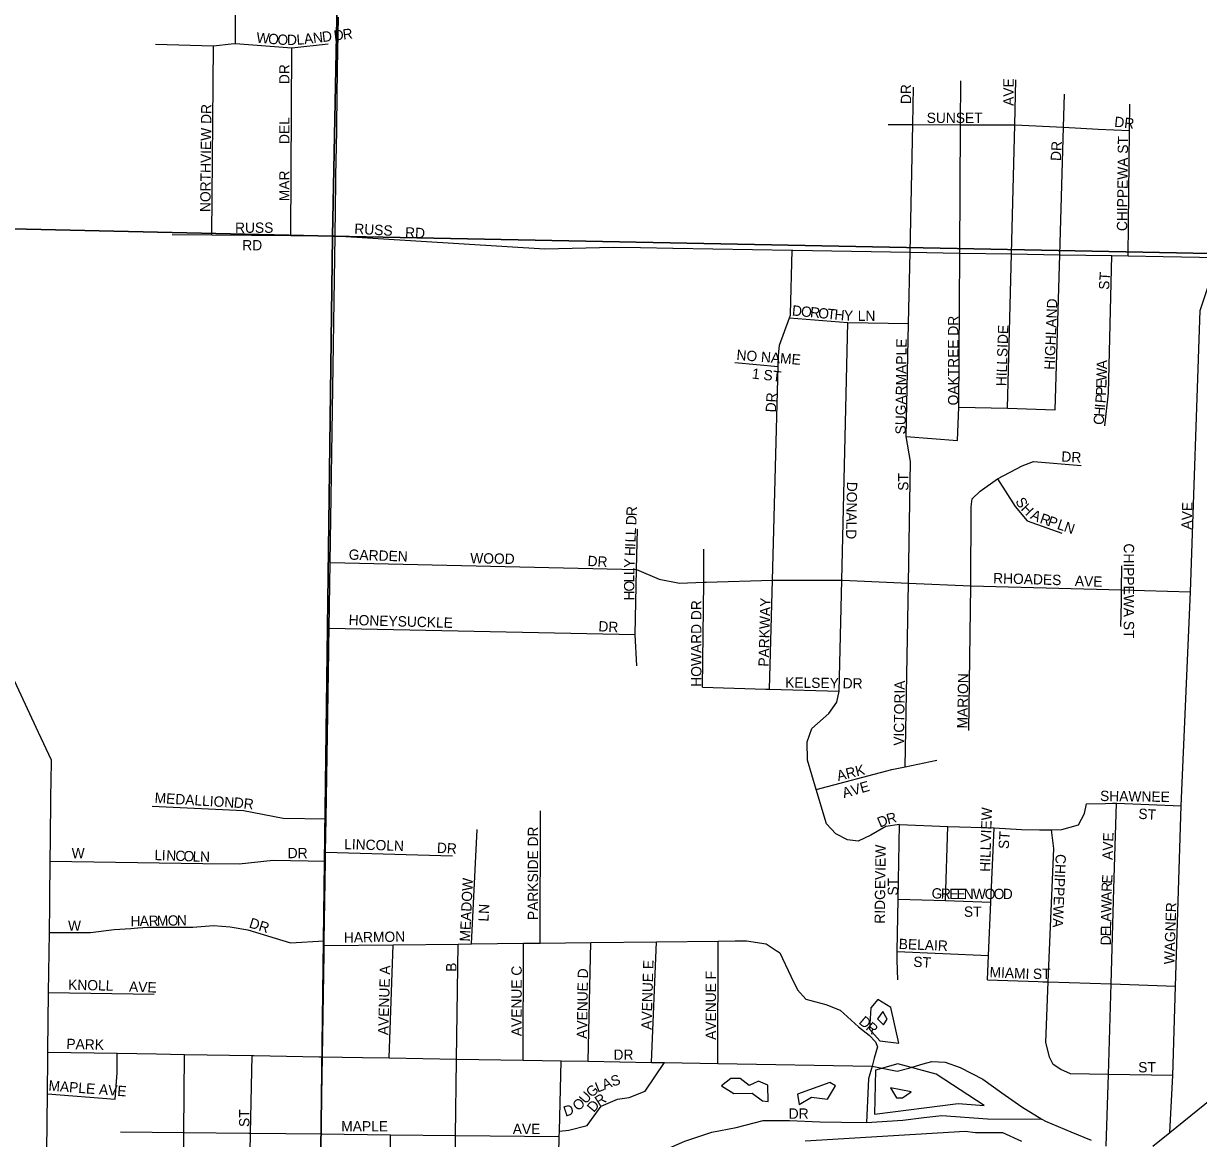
# Model space of a CAD drawing. Extents: x -784 to 1375, y -225 to 440.
# Drawn here: x 287.9 to 310.15, y 368.36 to 389.47 of the extents above; entities that cross this region are included whole.
import ezdxf

# ---------------------------------------------------------------- set-up
doc = ezdxf.new("R2010")
doc.units = 0
for name, color, linetype in [('GM_X_City_Street', 7, 'Continuous'), ('GM_X_City_Street_Text', 7, 'Continuous'), ('GM_X_Major_River', 7, 'Continuous'), ('GM_X_Minor_Lake', 7, 'Continuous'), ('GM_X_Section', 7, 'Continuous'), ('GM_X_State_Route', 7, 'Continuous'), ('GM_X_Township_Subdivision', 7, 'Continuous')]:
    doc.layers.add(name, color=color, linetype=linetype)

msp = doc.modelspace()

# ---------------------------------------------------------------- linework, layer by layer
at = {"layer": 'GM_X_City_Street'}
for points in [[(290.396, 389.08), (291.499, 389.046), (291.828, 389.084), (291.83, 389.084)], [(291.465, 385.468), (291.499, 389.046)], [(291.83, 389.084), (291.91, 389.093), (292.977, 389.009), (293.668, 389.089)], [(292.96, 385.456), (292.977, 389.009)], [(304.615, 381.651), (304.659, 383.79), (304.686, 385.14), (304.736, 387.556), (304.75, 388.263)], [(305.611, 382.209), (305.628, 385.124), (305.641, 387.555), (305.646, 388.384)], [(306.534, 382.188), (306.606, 385.108), (306.667, 387.554), (306.688, 388.407)], [(304.615, 381.651), (305.586, 381.577), (305.611, 382.209), (306.534, 382.188), (307.432, 382.155), (307.52, 385.092), (307.593, 387.506), (307.612, 388.136)], [(308.813, 385.07), (308.843, 387.442), (308.849, 387.944)], [(304.274, 387.557), (304.736, 387.556), (305.641, 387.555), (306.667, 387.554), (307.593, 387.506), (308.249, 387.473)], [(308.249, 387.473), (308.249, 387.473), (308.843, 387.442)], [(309.607, 368.471), (309.66, 369.552), (309.713, 371.243), (309.818, 374.657), (309.997, 378.712), (310.179, 384.035), (310.514, 385.041), (310.857, 386.101)], [(290.711, 385.475), (291.465, 385.468), (292.96, 385.456), (293.798, 385.449)], [(293.798, 385.449), (297.768, 385.203), (299.065, 385.236), (299.581, 385.228), (300.191, 385.217)], [(300.191, 385.217), (300.2, 385.217), (302.456, 385.179), (302.462, 385.178)], [(302.425, 383.956), (302.425, 383.965), (302.456, 385.179)], [(302.462, 385.178), (302.469, 385.178), (304.686, 385.14), (305.628, 385.124), (306.606, 385.108), (307.52, 385.092), (308.506, 385.075), (308.813, 385.07), (309.482, 385.059)], [(308.376, 381.851), (308.445, 382.468), (308.506, 385.075)], [(309.482, 385.059), (309.482, 385.059), (310.514, 385.041)], [(302.025, 376.867), (302.081, 378.931), (302.191, 382.973), (302.197, 383.184), (302.211, 383.379), (302.406, 383.897), (302.424, 383.945), (302.425, 383.956)], [(302.406, 383.897), (303.508, 383.81), (304.659, 383.79)], [(304.489, 374.303), (304.229, 374.263), (303.943, 374.1), (303.704, 373.99), (303.501, 374.011), (303.278, 374.128), (303.104, 374.314), (302.908, 374.969), (302.742, 375.524), (302.737, 375.869), (302.823, 376.118), (303.145, 376.405), (303.301, 376.622), (303.346, 376.83), (303.395, 378.929), (303.508, 383.81)], [(301.371, 383.052), (302.191, 382.973)], [(304.596, 375.398), (304.655, 378.875), (304.695, 381.179), (304.615, 381.651)], [(305.796, 376.081), (305.835, 378.823), (305.842, 380.32), (305.862, 380.469), (306.015, 380.613), (306.344, 380.846), (306.81, 381.096), (307.024, 381.177), (307.926, 381.101)], [(306.344, 380.846), (306.674, 380.323), (306.904, 380.051), (307.558, 379.817)], [(299.51, 377.309), (299.481, 377.898), (299.504, 379.135), (299.528, 379.895)], [(300.758, 376.902), (300.778, 378.89), (300.784, 379.519)], [(293.704, 379.266), (299.504, 379.135)], [(299.504, 379.135), (299.937, 378.95), (300.318, 378.875), (300.778, 378.89), (300.827, 378.891), (302.081, 378.931), (302.133, 378.931)], [(308.687, 378.515), (308.691, 378.747), (308.699, 379.203)], [(302.133, 378.931), (302.142, 378.931), (303.395, 378.929), (303.404, 378.929), (304.655, 378.875), (305.835, 378.823), (308.691, 378.747), (309.997, 378.712)], [(308.68, 378.052), (308.687, 378.513), (308.687, 378.515)], [(293.684, 378.021), (299.481, 377.898)], [(300.758, 376.902), (301.952, 376.869)], [(301.952, 376.869), (301.952, 376.869), (302.025, 376.867), (303.346, 376.83)], [(302.908, 374.969), (304.338, 375.346), (304.596, 375.398), (305.192, 375.519)], [(304.489, 374.303), (305.404, 374.267), (306.279, 374.24), (306.798, 374.209), (307.136, 374.202), (307.363, 374.204), (307.379, 374.204), (307.56, 374.207), (307.877, 374.294), (307.992, 374.511), (308.03, 374.693), (308.384, 374.703), (308.518, 374.707)], [(308.518, 374.707), (308.594, 374.709), (309.818, 374.657)], [(308.546, 373.085), (308.546, 373.085), (308.594, 374.709)], [(290.332, 374.651), (292.067, 374.567), (292.814, 374.426), (293.629, 374.409)], [(297.68, 372.058), (297.687, 374.559)], [(304.452, 371.364), (304.441, 371.733), (304.444, 371.897), (304.462, 372.892), (304.489, 374.303)], [(305.36, 372.861), (305.404, 374.267)], [(296.381, 372.043), (296.486, 374.211)], [(306.151, 371.359), (306.172, 371.821), (306.217, 372.831), (306.279, 374.24)], [(307.303, 371.322), (307.303, 371.328), (307.41, 373.851), (307.363, 374.204)], [(288.404, 373.606), (291.292, 373.564), (291.981, 373.558), (292.625, 373.625), (293.617, 373.61)], [(293.619, 373.782), (296.024, 373.708)], [(308.402, 368.215), (308.442, 369.57), (308.493, 371.283), (308.546, 373.085)], [(304.462, 372.892), (305.36, 372.861), (306.217, 372.831)], [(288.388, 372.257), (289.169, 372.257), (289.617, 372.314), (289.931, 372.336), (290.06, 372.344), (290.065, 372.345)], [(290.065, 372.345), (290.253, 372.357), (290.707, 372.359), (291.106, 372.362), (291.498, 372.389), (291.811, 372.364), (292.145, 372.307), (292.952, 372.062), (293.593, 372.098)], [(293.592, 372.011), (294.9, 372.026), (296.129, 372.04), (296.381, 372.043), (297.366, 372.055), (297.68, 372.058), (298.641, 372.069), (299.887, 372.083), (301.053, 372.097), (301.377, 372.1), (301.379, 372.1)], [(294.825, 369.883), (294.9, 372.026)], [(296.099, 369.84), (296.1, 369.861), (296.129, 372.04)], [(297.36, 369.84), (297.366, 372.055)], [(298.588, 369.819), (298.641, 372.069)], [(299.793, 369.798), (299.887, 372.083)], [(301.045, 369.777), (301.053, 372.097)], [(301.379, 372.1), (301.587, 372.103), (301.961, 372.044), (302.17, 371.906), (302.174, 371.903)], [(302.174, 371.903), (302.222, 371.872), (302.427, 371.434), (302.552, 371.172), (302.711, 370.994), (303.092, 370.896), (303.362, 370.786), (303.712, 370.47), (303.911, 370.315), (304.032, 370.185), (304.069, 370.09), (304.007, 369.881), (303.966, 369.727), (303.901, 369.484), (303.86, 368.662)], [(304.444, 371.897), (306.172, 371.821)], [(306.151, 371.359), (307.111, 371.328)], [(307.111, 371.328), (307.198, 371.325), (307.303, 371.322), (308.493, 371.283), (309.713, 371.243)], [(309.66, 369.552), (308.442, 369.57), (307.727, 369.581), (307.54, 369.664), (307.393, 369.761), (307.326, 369.896), (307.254, 370.18), (307.303, 371.322)], [(288.374, 371.122), (290.37, 371.091)], [(288.36, 369.993), (289.669, 369.971), (290.414, 369.958), (290.414, 369.958)], [(289.635, 369.099), (289.674, 369.6), (289.669, 369.971)], [(290.414, 369.958), (290.945, 369.949), (292.227, 369.927), (292.262, 369.927), (292.262, 369.927)], [(290.927, 367.203), (290.935, 368.472), (290.945, 369.949)], [(292.135, 365.382), (292.136, 365.399), (292.169, 367.021), (292.198, 368.458), (292.227, 369.927)], [(292.262, 369.927), (293.494, 369.906)], [(293.494, 369.906), (293.494, 369.906), (293.56, 369.904), (294.315, 369.891)], [(294.315, 369.891), (294.315, 369.891), (294.825, 369.883), (296.1, 369.861), (297.36, 369.84), (298.079, 369.827), (298.588, 369.819), (299.793, 369.798), (300.037, 369.794), (301.045, 369.777), (303.966, 369.727), (304.444, 369.633), (304.665, 369.69), (304.934, 369.77), (305.1, 369.814), (305.351, 369.8), (305.632, 369.7), (306.066, 369.478), (306.422, 369.219), (306.801, 368.96), (307.184, 368.724), (307.25, 368.683), (307.733, 368.484), (308.114, 368.327)], [(296.062, 367.039), (296.08, 368.416), (296.099, 369.84), (296.099, 369.84)], [(298.364, 366.766), (298.018, 367.055), (298.043, 368.394), (298.046, 368.496), (298.079, 369.827)], [(298.046, 368.496), (298.227, 368.514), (298.574, 368.605), (298.838, 368.97), (299.146, 369.105), (299.369, 369.131), (299.672, 369.255), (300.037, 369.794)], [(288.351, 369.202), (289.635, 369.099)], [(298.294, 366.575), (298.336, 366.731), (298.364, 366.766), (298.695, 367.183), (299.011, 367.541), (299.395, 367.804), (299.928, 368.093), (300.42, 368.306), (300.934, 368.478), (301.391, 368.566), (301.904, 368.699), (302.405, 368.699), (302.976, 368.674), (303.39, 368.669), (303.86, 368.662), (304.548, 368.706), (304.949, 368.752), (305.288, 368.791), (306.151, 368.732), (307.184, 368.724)], [(289.733, 368.485), (290.935, 368.472), (292.166, 368.459), (292.172, 368.458)], [(292.172, 368.458), (292.198, 368.458), (293.537, 368.444), (294.85, 368.429), (296.08, 368.416), (298.043, 368.394)], [(294.841, 365.852), (294.85, 368.429)]]:
    msp.add_lwpolyline(points, dxfattribs=at)
at = {"layer": 'GM_X_Major_River'}
for points in [[(304.168, 370.761), (304.072, 370.621), (304.18, 370.51)], [(304.18, 370.51), (304.252, 370.619), (304.168, 370.761)], [(304.705, 369.241), (304.315, 369.317), (304.43, 369.127)], [(304.43, 369.127), (304.54, 369.126), (304.705, 369.241)], [(306.803, 368.299), (306.443, 368.464), (305.925, 368.464), (305.73, 368.491), (302.701, 368.307)]]:
    msp.add_lwpolyline(points, dxfattribs=at)
at = {"layer": 'GM_X_Minor_Lake'}
for points in [[(304.076, 370.989), (303.941, 370.834), (303.921, 370.427), (304.114, 370.205), (304.474, 370.161)], [(304.474, 370.161), (304.325, 370.837), (304.076, 370.989)], [(305.179, 369.573), (304.453, 369.77), (304.029, 369.649), (304.011, 368.819)], [(304.011, 368.819), (305.595, 369.019), (306.088, 368.981), (305.179, 369.573)], [(301.638, 369.358), (301.467, 369.493), (301.295, 369.495), (301.113, 369.356), (301.346, 369.212), (301.699, 369.216), (301.893, 369.072)], [(301.893, 369.072), (302.002, 369.055), (301.99, 369.369), (301.819, 369.442), (301.638, 369.358)], [(303.274, 369.353), (303.165, 369.417), (302.552, 369.198), (302.589, 369.001)], [(302.589, 369.001), (302.817, 369.139), (303.122, 369.104), (303.274, 369.353)]]:
    msp.add_lwpolyline(points, dxfattribs=at)
at = {"layer": 'GM_X_Section'}
for points in [[(311.752, 405.896), (315.331, 405.821), (314.846, 385.028), (293.747, 385.447), (294.035, 399.712)], [(294.035, 399.712), (293.747, 385.447), (273.043, 385.919), (273.347, 399.712)]]:
    msp.add_lwpolyline(points, dxfattribs=at)
for points in [[(273.043, 385.919), (293.747, 385.447), (293.485, 364.699), (272.601, 365.183)], [(293.747, 385.447), (314.846, 385.028), (314.451, 364.338), (293.485, 364.699)]]:
    msp.add_lwpolyline(points, close=True, dxfattribs=at)
at = {"layer": 'GM_X_State_Route'}
for points in [[(293.847, 388.603), (293.847, 388.616), (293.862, 389.589)], [(293.823, 387.026), (293.847, 388.603)], [(293.798, 385.449), (293.798, 385.449), (293.822, 386.981), (293.823, 387.026)], [(293.679, 377.675), (293.684, 378.021), (293.704, 379.266), (293.798, 385.449)], [(288.426, 375.358), (288.428, 375.519), (288.184, 376.044), (284.428, 384.117)], [(293.591, 371.947), (293.592, 372.011), (293.593, 372.098), (293.617, 373.61), (293.619, 373.782), (293.629, 374.409), (293.678, 377.585), (293.679, 377.675)], [(288.411, 374.127), (288.425, 375.271), (288.426, 375.358)], [(288.396, 372.896), (288.404, 373.606), (288.41, 374.03), (288.411, 374.127)], [(288.361, 370.023), (288.374, 371.122), (288.388, 372.257), (288.394, 372.79), (288.396, 372.896)], [(293.458, 363.284), (293.48, 364.725), (293.498, 365.868), (293.516, 367.037), (293.537, 368.444), (293.56, 369.904), (293.59, 371.864), (293.591, 371.947)], [(288.325, 367.035), (288.351, 369.202), (288.359, 369.895), (288.36, 369.993), (288.361, 370.023)], [(309.286, 368.21), (309.607, 368.471), (310.402, 369.115)]]:
    msp.add_lwpolyline(points, dxfattribs=at)
at = {"layer": 'GM_X_Township_Subdivision'}
msp.add_lwpolyline([(291.91, 389.093), (291.915, 390.138)], dxfattribs=at)

# ---------------------------------------------------------------- texts
at = {"layer": 'GM_X_City_Street_Text'}
for s, height, rotation, p in [('R', 0.195, 6.8086, (293.954, 389.165)), ('W', 0.195, 354.5576, (292.301, 389.111)), ('O', 0.195, 354.5576, (292.523, 389.09)), ('O', 0.195, 356.5994, (292.702, 389.073)), ('D', 0.195, 0.6831, (292.889, 389.063)), ('L', 0.195, 4.7668, (293.076, 389.066)), ('A', 0.195, 6.8086, (293.22, 389.078)), ('N', 0.195, 6.8086, (293.391, 389.098)), ('D', 0.195, 6.8086, (293.562, 389.119)), ('D', 0.195, 6.8086, (293.784, 389.145)), ('DR', 0.1953, 90, (292.935, 388.323)), ('DR', 0.1953, 90, (304.706, 387.945)), ('AVE', 0.1953, 90, (306.648, 387.911)), ('NORTHVIEW DR', 0.19531, 89.4643, (291.438, 385.9)), ('DEL', 0.1953, 90, (292.935, 387.189)), ('SUNSET', 0.1953, 0, (305.001, 387.587)), ('DR', 0.1953, 353.6635, (308.546, 387.518)), ('DR', 0.1953, 86.9861, (307.542, 386.864)), ('CHIPPEWA ST', 0.19531, 89.3701, (308.797, 385.539)), ('MAR', 0.1953, 90, (292.935, 386.106)), ('RUSS', 0.1953, 0, (291.904, 385.507)), ('RUSS', 0.1953, 356.7313, (294.158, 385.49)), ('RD', 0.1953, 356.9887, (295.12, 385.421)), ('RD', 0.1953, 0, (292.041, 385.175)), ('ST', 0.1953, 86.4254, (308.453, 384.424)), ('HIGHLAND', 0.1953, 87.6464, (307.422, 382.911)), ('D', 0.195, 354.5493, (302.444, 383.943)), ('O', 0.195, 354.5608, (302.615, 383.926)), ('R', 0.195, 354.5522, (302.786, 383.91)), ('O', 0.195, 354.5493, (302.94, 383.895)), ('T', 0.195, 354.5523, (303.111, 383.879)), ('H', 0.195, 354.5608, (303.248, 383.866)), ('Y', 0.195, 356.9387, (303.428, 383.849)), ('LN', 0.1953, 0, (303.695, 383.84)), ('OAKTREE DR', 0.1953, 90, (305.6, 382.239)), ('HILLSIDE', 0.1953, 88.1525, (306.511, 382.601)), ('SUGARMAPLE', 0.1953, 89.3908, (304.603, 381.689)), ('NO NAME', 0.1953, 355.5353, (301.394, 383.101)), ('1 ST', 0.1953, 353.6631, (301.685, 382.749)), ('W', 0.195, 88.495, (308.408, 382.699)), ('A', 0.195, 88.492, (308.414, 382.923)), ('E', 0.195, 88.4114, (308.404, 382.562)), ('P', 0.195, 87.1481, (308.397, 382.419)), ('DR', 0.1953, 86.9861, (302.145, 382.103)), ('I', 0.195, 85.1311, (308.378, 382.189)), ('P', 0.195, 85.278, (308.385, 382.276)), ('C', 0.195, 85.1315, (308.35, 381.864)), ('H', 0.195, 85.1363, (308.363, 382.018)), ('DR', 0.1953, 356.9889, (307.547, 381.176)), ('ST', 0.1953, 90, (304.655, 380.623)), ('DONALD', 0.1953, 269.0285, (303.491, 380.795)), ('S', 0.195, 301.6608, (306.672, 380.423)), ('R', 0.195, 87.5766, (299.507, 380.139)), ('H', 0.195, 314.0555, (306.772, 380.269)), ('AVE', 0.1953, 88.0242, (310.017, 379.886)), ('D', 0.195, 87.584, (299.5, 379.967)), ('A', 0.195, 333.9434, (306.951, 380.103)), ('R', 0.195, 341.3166, (307.131, 380.017)), ('P', 0.195, 340.8782, (307.277, 379.967)), ('L', 0.195, 340.8855, (307.456, 379.905)), ('N', 0.195, 340.8722, (307.586, 379.86)), ('L', 0.195, 87.5793, (299.492, 379.778)), ('I', 0.195, 87.5922, (299.482, 379.555)), ('L', 0.195, 87.5742, (299.486, 379.641)), ('CHIPPEWA ST', 0.19531, 270, (308.733, 379.626)), ('GARDEN', 0.1953, 358.0224, (294.054, 379.319)), ('WOOD', 0.1953, 358.9197, (296.356, 379.251)), ('DR', 0.1953, 356.9774, (298.575, 379.199)), ('H', 0.195, 87.5806, (299.475, 379.383)), ('L', 0.195, 89.194, (299.464, 379.024)), ('Y', 0.195, 87.836, (299.466, 379.16)), ('L', 0.195, 89.9764, (299.464, 378.887)), ('RHOADES', 0.1953, 358.2652, (306.257, 378.873)), ('AVE', 0.1953, 358.0261, (307.804, 378.821)), ('O', 0.195, 89.9727, (299.464, 378.715)), ('H', 0.195, 89.9781, (299.464, 378.544)), ('HOWARD DR', 0.1953, 90, (300.736, 376.911)), ('PARKWAY', 0.1953, 88.3635, (302.008, 377.29)), ('HONEYSUCKLE', 0.19531, 358.3326, (294.053, 378.082)), ('DR', 0.1953, 356.9889, (298.781, 377.962)), ('MARION', 0.1953, 88.9775, (305.772, 376.121)), ('KELSEY DR', 0.1953, 359.2466, (302.32, 376.896)), ('VICTORIA', 0.1953, 89.1316, (304.569, 375.794)), ('ARK', 0.1953, 14.0362, (303.325, 375.125)), ('AVE', 0.1953, 15.9511, (303.433, 374.801)), ('SHAWNEE', 0.1953, 359.1592, (308.283, 374.748)), ('MEDALLION', 0.1953, 356.5518, (290.377, 374.713)), ('DR', 0.1953, 353.9913, (291.872, 374.627)), ('D', 0.195, 23.4232, (304.117, 374.241)), ('R', 0.195, 14.5325, (304.267, 374.306)), ('HILLVIEW', 0.1953, 88.3154, (306.202, 373.406)), ('ST', 0.1953, 356.4256, (309.004, 374.412)), ('PARKSIDE DR', 0.19531, 90, (297.642, 372.494)), ('LINCOLN', 0.1953, 358.1196, (293.968, 373.837)), ('ST', 0.1953, 86.4254, (306.554, 373.833)), ('AVE', 0.1953, 88.0242, (308.522, 373.629)), ('W', 0.195, 0, (288.81, 373.665)), ('L', 0.195, 357.8412, (290.376, 373.63)), ('I', 0.195, 357.8652, (290.513, 373.625)), ('N', 0.195, 357.8575, (290.599, 373.622)), ('C', 0.195, 357.8382, (290.771, 373.616)), ('O', 0.195, 357.8592, (290.925, 373.61)), ('L', 0.195, 357.9616, (291.098, 373.603)), ('DR', 0.1953, 0, (292.901, 373.665)), ('DR', 0.1953, 356.8219, (295.722, 373.768)), ('RIDGEVIEW', 0.1953, 89.2756, (304.208, 372.424)), ('N', 0.195, 359.2973, (291.24, 373.598)), ('CHIPPEWA', 0.1953, 267.581, (307.444, 373.747)), ('MEADOW', 0.1953, 87.3159, (296.353, 372.083)), ('ST', 0.1953, 90, (304.458, 372.958)), ('R', 0.195, 87.4675, (308.504, 373.025)), ('E', 0.195, 86.4799, (308.511, 373.179)), ('G', 0.195, 356.5007, (305.089, 372.908)), ('R', 0.195, 357.861, (305.266, 372.898)), ('E', 0.195, 359.8291, (305.428, 372.892)), ('E', 0.195, 359.9956, (305.566, 372.891)), ('N', 0.195, 0, (305.703, 372.891)), ('W', 0.195, 0, (305.875, 372.891)), ('O', 0.195, 0, (306.099, 372.891)), ('O', 0.195, 0, (306.27, 372.891)), ('D', 0.195, 0, (306.442, 372.891)), ('A', 0.195, 88.9836, (308.501, 372.855)), ('LN', 0.1953, 86.9884, (296.702, 372.461)), ('ST', 0.1953, 0, (305.706, 372.555)), ('W', 0.195, 89.0644, (308.498, 372.632)), ('WAGNER', 0.1953, 88.1222, (309.691, 371.653)), ('W', 0.195, 0, (288.741, 372.29)), ('H', 0.195, 0.9399, (289.927, 372.376)), ('A', 0.195, 0.9702, (290.099, 372.379)), ('R', 0.195, 0.9472, (290.271, 372.381)), ('M', 0.195, 0.9472, (290.425, 372.384)), ('O', 0.195, 0.9399, (290.632, 372.387)), ('N', 0.195, 0.9702, (290.804, 372.39)), ('DR', 0.1953, 342.4731, (292.156, 372.357)), ('A', 0.195, 89.0637, (308.495, 372.46)), ('HARMON', 0.1953, 0.9235, (293.966, 372.066)), ('E', 0.195, 89.0556, (308.49, 372.185)), ('L', 0.195, 89.0643, (308.493, 372.322)), ('BELAIR', 0.1953, 357.7107, (304.469, 371.946)), ('D', 0.195, 89.0655, (308.488, 372.013)), ('ST', 0.1953, 356.4256, (304.742, 371.611)), ('AVENUE A', 0.1953, 88.3866, (294.806, 370.312)), ('B', 0.195, 90, (296.095, 371.514)), ('AVENUE C', 0.1953, 90, (297.333, 370.294)), ('AVENUE E', 0.1953, 88.339, (299.791, 370.415)), ('MIAMI', 0.1953, 357.3989, (306.188, 371.413)), ('ST', 0.1953, 0, (307.012, 371.379)), ('KNOLL', 0.1953, 358.7818, (288.742, 371.173)), ('AVENUE D', 0.1953, 89.1927, (298.57, 370.243)), ('AVENUE F', 0.1953, 90, (301.011, 370.225)), ('AVE', 0.1953, 357.9558, (289.894, 371.138)), ('D', 0.195, 319.5682, (303.701, 370.545)), ('R', 0.195, 320.0296, (303.834, 370.432)), ('PARK', 0.1953, 358.4527, (288.708, 370.053)), ('DR', 0.1953, 0, (299.071, 369.847)), ('ST', 0.1953, 0, (309.006, 369.609)), ('MAPLE AVE', 0.1953, 355.6564, (288.366, 369.265)), ('G', 0.195, 40.4318, (298.653, 369.123)), ('L', 0.195, 21.6898, (298.77, 369.225)), ('A', 0.195, 21.6975, (298.898, 369.276)), ('S', 0.195, 17.7114, (299.054, 369.339)), ('U', 0.195, 48.6366, (298.545, 368.999)), ('R', 0.195, 32.6798, (298.796, 368.96)), ('ST', 0.1953, 90, (292.177, 368.575)), ('D', 0.195, 17.7214, (298.159, 368.769)), ('O', 0.195, 42.1649, (298.401, 368.866)), ('D', 0.195, 50.1567, (298.698, 368.839)), ('DR', 0.1953, 0, (302.388, 368.732)), ('MAPLE', 0.1953, 0, (293.915, 368.491)), ('AVE', 0.1953, 0, (297.163, 368.44))]:
    msp.add_text(s, height=height, rotation=rotation, dxfattribs=at).set_placement(p)

doc.saveas('drawing.dxf')
